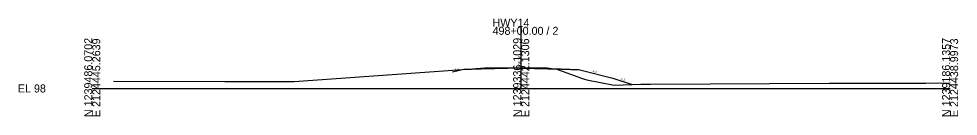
# Model space of a CAD drawing. Extents: x -26 to 303, y -10 to 11521.
# Drawn here: x -25.7 to 302.8, y 9490.3 to 9524.4 of the extents above; entities that cross this region are included whole.
import ezdxf

# ---------------------------------------------------------------- set-up
doc = ezdxf.new("R2010")
doc.units = 0
for name, color, linetype in [('XS_CELL', 7, 'Continuous'), ('XS_P_FINISHED_GRADE', 7, 'Continuous'), ('XS_P_SUBGRADE_GRANULAR', 7, 'Continuous'), ('XS_P_SUBGRADE_LEVELING', 7, 'Continuous'), ('XS_P_TX_FS_BS', 7, 'Continuous'), ('XS_X_GROUND', 7, 'Continuous'), ('XS_X_GROUND_TX', 7, 'Continuous')]:
    doc.layers.add(name, color=color, linetype=linetype)

msp = doc.modelspace()

# ---------------------------------------------------------------- linework, layer by layer
at = {"layer": 'XS_CELL'}
for p, q in [((150, 9500), (150, 9521.55)), ((0, 9500), (150, 9500)), ((150, 9500), (300, 9500))]:
    msp.add_line(p, q, dxfattribs=at)
at = {"layer": 'XS_P_FINISHED_GRADE'}
for p, q in [((130, 9506.66), (126, 9505.66)), ((136, 9506.9), (130, 9506.66)), ((150, 9507.18), (136, 9506.9)), ((150, 9507.18), (164, 9506.9)), ((164, 9506.9), (170, 9506.66)), ((170, 9506.66), (182, 9503.66)), ((182, 9503.66), (188.79, 9501.4))]:
    msp.add_line(p, q, dxfattribs=at)
at = {"layer": 'XS_P_SUBGRADE_GRANULAR'}
for p, q in [((136, 9506.77), (129.4, 9506.51)), ((164, 9506.77), (170.6, 9506.51))]:
    msp.add_line(p, q, dxfattribs=at)
at = {"layer": 'XS_P_SUBGRADE_LEVELING'}
for p, q in [((150, 9507.05), (136, 9506.77)), ((136, 9506.77), (136, 9506.9)), ((150, 9507.05), (164, 9506.77)), ((164, 9506.77), (164, 9506.9))]:
    msp.add_line(p, q, dxfattribs=at)
at = {"layer": 'XS_X_GROUND'}
for p, q in [((70.65, 9502.4), (131.02, 9506.75)), ((131.02, 9506.75), (133.22, 9506.84)), ((133.22, 9506.84), (134.17, 9506.97)), ((134.17, 9506.97), (137.3, 9507.17)), ((137.3, 9507.17), (141.29, 9507.17)), ((141.29, 9507.17), (150, 9507.18)), ((150, 9507.18), (159.18, 9507.18)), ((159.18, 9507.18), (160.56, 9507.02)), ((160.56, 9507.02), (162.08, 9506.88)), ((162.08, 9506.88), (171.13, 9503.59)), ((7.41, 9502.57), (46.4, 9502.47)), ((46.4, 9502.47), (70.65, 9502.4)), ((171.13, 9503.59), (172.1, 9503.24)), ((172.1, 9503.24), (172.99, 9503.07)), ((172.99, 9503.07), (182.57, 9501.17)), ((182.57, 9501.17), (191.82, 9501.51)), ((191.82, 9501.51), (192.22, 9501.52)), ((192.22, 9501.52), (195.25, 9501.54)), ((195.25, 9501.54), (257.7, 9501.83)), ((257.7, 9501.83), (291.48, 9501.91)), ((291.48, 9501.91), (300, 9501.93))]:
    msp.add_line(p, q, dxfattribs=at)

# ---------------------------------------------------------------- texts
at = {"layer": 'XS_CELL'}
for s, p in [('HWY14', (140, 9521.55)), ('498+00.00 / 2', (140, 9518.75)), ('EL 98', (-26, 9498.6))]:
    msp.add_text(s, height=2.8, dxfattribs=at).set_placement(p)
for s, p in [('N 1239486.0702', (0, 9490)), ('E 2124445.2639', (2.8, 9490)), ('N 1239336.1029', (150, 9490)), ('E 2124442.1306', (152.8, 9490)), ('N 1239186.1357', (300, 9490)), ('E 2124438.9973', (302.8, 9490))]:
    msp.add_text(s, height=2.8, rotation=90, dxfattribs=at).set_placement(p)
at = {"layer": 'XS_P_TX_FS_BS'}
for s, rotation, p in [('4:1', 14.0362, (126.88, 9506.05)), ('4:1', 345.9638, (174.9, 9505.7)), ('3:1', 341.5651, (184.71, 9503.03))]:
    msp.add_text(s, height=0.8, rotation=rotation, dxfattribs=at).set_placement(p)
at = {"layer": 'XS_X_GROUND_TX'}
msp.add_text('105.18', height=1, rotation=90, dxfattribs=at).set_placement((150, 9507.28))

doc.saveas('drawing.dxf')
